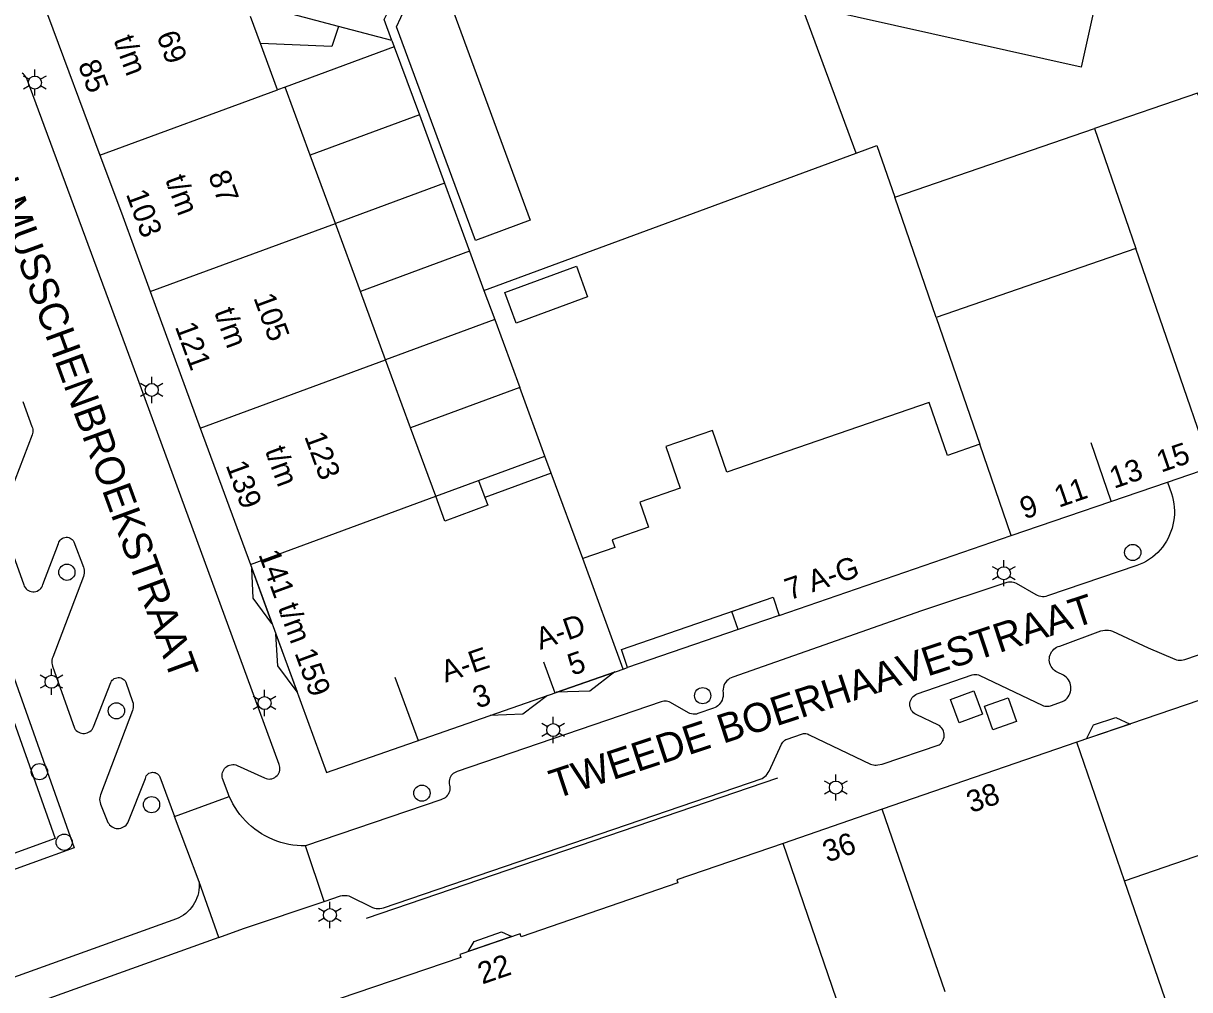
# Model space of a CAD drawing. Extents: x 122462 to 123306, y 485548 to 486417.
# Drawn here: x 122543.2 to 122623.8, y 485773.2 to 485839.9 of the extents above; entities that cross this region are included whole.
import ezdxf

# ---------------------------------------------------------------- set-up
doc = ezdxf.new("R2010")
doc.units = 0
for name, color, linetype in [('Level 1', 7, 'Continuous'), ('Level 10', 7, 'Continuous'), ('Level 17', 7, 'Continuous'), ('Level 19', 7, 'Continuous'), ('Level 2', 7, 'Continuous'), ('Level 22', 7, 'Continuous'), ('Level 23', 7, 'Continuous'), ('Level 24', 7, 'Continuous'), ('Level 4', 7, 'Continuous'), ('Level 42', 7, 'Continuous'), ('Level 45', 7, 'Continuous'), ('Level 5', 7, 'Continuous'), ('Level 50', 7, 'Continuous'), ('Level 53', 7, 'Continuous'), ('Level 58', 7, 'Continuous'), ('Level 59', 7, 'Continuous')]:
    doc.layers.add(name, color=color, linetype=linetype)

msp = doc.modelspace()

# ---------------------------------------------------------------- linework, layer by layer
at = {"layer": 'Level 1'}
for p, q in [((122559.59, 485838.478), (122558.901, 485840.349)), ((122560.77, 485835.277), (122559.59, 485838.478)), ((122561.299, 485835.472), (122560.77, 485835.277)), ((122563.031, 485830.771), (122561.299, 485835.472)), ((122617.208, 485832.614), (122620.063, 485824.326)), ((122564.766, 485826.061), (122563.031, 485830.771)), ((122566.498, 485821.36), (122564.766, 485826.061)), ((122620.063, 485824.326), (122606.271, 485819.574)), ((122551.983, 485821.351), (122555.439, 485811.934)), ((122568.234, 485816.648), (122566.498, 485821.36)), ((122606.271, 485819.574), (122609.291, 485810.81)), ((122569.966, 485811.947), (122568.234, 485816.648)), ((122555.439, 485811.934), (122558.897, 485802.507)), ((122571.706, 485807.226), (122569.966, 485811.947)), ((122622.246, 485808.207), (122625.259, 485809.239)), ((122579.676, 485808.83), (122575.095, 485807.142)), ((122581.851, 485802.93), (122579.676, 485808.83)), ((122611.459, 485804.509), (122622.246, 485808.207)), ((122584.64, 485795.299), (122584.954, 485795.401)), ((122624.403, 485793.12), (122615.979, 485790.239)), ((122615.979, 485790.239), (122602.549, 485785.62)), ((122602.549, 485785.62), (122595.705, 485783.261)), ((122622.308, 485771.864), (122619.273, 485780.677))]:
    msp.add_line(p, q, dxfattribs=at)
for points in [[(122546.889, 485845.419), (122544.88, 485840.66), (122544.88, 485840.489), (122548.508, 485830.759)], [(122633.776, 485812.174), (122633.562, 485812.799), (122633.411, 485812.748), (122629.727, 485823.472), (122624.31, 485835.061), (122617.208, 485832.614)], [(122548.508, 485830.759), (122549.989, 485826.779), (122551.983, 485821.351)], [(122609.291, 485810.81), (122607.042, 485810.035), (122605.779, 485813.701), (122591.812, 485808.889), (122590.818, 485811.775), (122587.595, 485810.664), (122588.589, 485807.778), (122585.805, 485806.819), (122586.404, 485805.081), (122583.892, 485804.215), (122584.071, 485803.695), (122581.851, 485802.93)], [(122575.095, 485807.142), (122575.295, 485806.599), (122572.338, 485805.51), (122571.706, 485807.226)], [(122584.954, 485795.401), (122584.524, 485796.649), (122595.002, 485800.25), (122595.429, 485798.999), (122611.459, 485804.509)], [(122558.897, 485802.507), (122564.16, 485788.16), (122584.64, 485795.299)], [(122595.705, 485783.261), (122588.35, 485780.749), (122588.42, 485780.539), (122577.601, 485776.821), (122577.531, 485777.031), (122573.371, 485775.601), (122573.443, 485775.393), (122562.65, 485771.719), (122562.57, 485771.939), (122555.33, 485769.42), (122555.347, 485769.372), (122554.835, 485769.176)], [(122619.273, 485780.677), (122624.837, 485782.58), (122625.179, 485781.58), (122628.017, 485782.551)]]:
    msp.add_lwpolyline(points, dxfattribs=at)
at = {"layer": 'Level 10'}
for points in [[(122560.385, 485798.453), (122559.094, 485800.197), (122558.994, 485802.244), (122560.385, 485798.453)], [(122592.594, 485798.026), (122592.166, 485799.275), (122595.002, 485800.25), (122595.429, 485798.999), (122592.594, 485798.026)], [(122562.118, 485793.73), (122560.794, 485795.514), (122560.66, 485797.702), (122562.118, 485793.73)], [(122580.046, 485793.699), (122584.079, 485795.105), (122582.34, 485793.768), (122580.046, 485793.699)], [(122575.454, 485792.098), (122579.425, 485793.482), (122577.708, 485792.175), (122575.454, 485792.098)], [(122616.657, 485790.472), (122617.13, 485791.436), (122618.682, 485791.946), (122619.676, 485791.504), (122616.657, 485790.472)], [(122573.935, 485775.795), (122574.363, 485776.484), (122576.242, 485777.16), (122576.96, 485776.835), (122573.935, 485775.795)]]:
    msp.add_lwpolyline(points, dxfattribs=at)
at = {"layer": 'Level 17'}
for p, q in [((122553.649, 485785.113), (122557.439, 485786.507)), ((122555.35, 485780.611), (122553.649, 485785.113)), ((122563.992, 485779.259), (122562.705, 485783.088)), ((122556.723, 485776.778), (122555.35, 485780.611))]:
    msp.add_line(p, q, dxfattribs=at)
for points in [[(122557.439, 485786.507), (122557.356, 485786.712), (122556.978, 485787.74), (122556.954, 485787.843), (122556.946, 485787.949), (122556.952, 485788.055), (122556.973, 485788.158), (122557.008, 485788.258), (122557.057, 485788.352), (122557.119, 485788.438), (122557.193, 485788.515), (122557.276, 485788.58), (122557.368, 485788.633), (122557.466, 485788.672), (122557.569, 485788.697), (122557.675, 485788.708), (122557.78, 485788.703), (122557.885, 485788.684), (122557.985, 485788.65), (122559.882, 485787.778), (122559.979, 485787.74), (122560.08, 485787.715), (122560.184, 485787.706), (122560.288, 485787.711), (122560.39, 485787.73), (122560.488, 485787.764), (122560.581, 485787.811), (122560.666, 485787.871), (122560.742, 485787.942), (122560.807, 485788.023), (122560.861, 485788.113), (122560.9, 485788.209), (122560.926, 485788.31), (122560.938, 485788.413), (122560.935, 485788.517), (122560.917, 485788.62), (122560.885, 485788.719), (122551.134, 485815.329), (122543.48, 485835.998), (122543.433, 485836.103), (122543.374, 485836.2), (122543.303, 485836.29), (122543.221, 485836.37), (122543.129, 485836.438)], [(122543.169, 485813.762), (122543.806, 485812.041), (122543.84, 485811.948), (122543.862, 485811.851), (122543.872, 485811.752), (122543.868, 485811.652), (122543.852, 485811.554), (122543.823, 485811.459), (122541.734, 485806)], [(122622.246, 485808.207), (122622.516, 485807.422), (122622.588, 485807.188), (122622.646, 485806.951), (122622.688, 485806.71), (122622.716, 485806.467), (122622.729, 485806.222), (122622.726, 485805.978), (122622.708, 485805.734), (122622.675, 485805.491), (122622.627, 485805.252), (122622.565, 485805.015), (122622.488, 485804.783), (122622.396, 485804.556), (122622.291, 485804.336), (122622.172, 485804.122), (122622.04, 485803.916), (122621.896, 485803.718), (122621.739, 485803.53), (122621.571, 485803.352), (122621.393, 485803.185), (122621.204, 485803.029), (122621.007, 485802.885), (122620.8, 485802.754), (122620.586, 485802.636), (122620.365, 485802.531), (122620.138, 485802.44), (122613.966, 485800.341), (122613.853, 485800.309), (122613.737, 485800.292), (122613.62, 485800.289), (122613.504, 485800.301), (122613.39, 485800.328), (122613.28, 485800.368), (122613.176, 485800.422), (122611.817, 485801.199), (122611.713, 485801.246), (122611.603, 485801.279), (122611.49, 485801.298), (122611.376, 485801.302), (122611.262, 485801.291), (122611.15, 485801.266), (122605.264, 485799.309), (122592.215, 485794.747), (122592.099, 485794.699), (122591.991, 485794.637), (122591.891, 485794.562), (122591.801, 485794.474), (122591.723, 485794.377), (122591.657, 485794.27), (122591.606, 485794.156), (122591.569, 485794.036), (122591.547, 485793.913), (122591.541, 485793.788), (122591.559, 485793.658), (122591.561, 485793.526), (122591.548, 485793.395), (122591.52, 485793.267), (122591.478, 485793.142), (122591.425, 485793.035), (122591.359, 485792.935), (122591.282, 485792.844), (122591.195, 485792.763), (122591.099, 485792.693), (122590.994, 485792.634), (122590.884, 485792.589), (122589.817, 485792.222), (122589.708, 485792.193), (122589.596, 485792.179), (122589.483, 485792.182), (122589.371, 485792.199), (122589.263, 485792.233), (122589.161, 485792.281), (122587.921, 485792.982), (122587.834, 485793.025), (122587.743, 485793.057), (122587.649, 485793.077), (122587.552, 485793.086), (122587.456, 485793.083), (122587.36, 485793.068), (122587.267, 485793.042), (122573.18, 485788.218), (122573.083, 485788.187), (122572.992, 485788.144), (122572.908, 485788.087), (122572.832, 485788.02), (122572.767, 485787.943), (122572.713, 485787.857), (122572.672, 485787.765), (122572.644, 485787.667), (122572.63, 485787.567), (122572.63, 485787.376), (122572.662, 485787.273), (122572.68, 485787.167), (122572.684, 485787.059), (122572.674, 485786.951), (122572.65, 485786.846), (122572.613, 485786.745), (122572.563, 485786.649), (122572.501, 485786.561), (122572.427, 485786.482)], [(122541.727, 485805.379), (122543.239, 485801.104), (122543.279, 485801.008), (122543.333, 485800.92), (122543.4, 485800.84), (122543.478, 485800.771), (122543.565, 485800.715), (122543.66, 485800.672), (122543.76, 485800.644), (122543.863, 485800.631), (122543.967, 485800.634), (122544.07, 485800.652), (122544.168, 485800.685), (122544.26, 485800.733), (122544.345, 485800.794), (122544.419, 485800.867), (122544.481, 485800.95), (122544.531, 485801.041), (122544.566, 485801.139), (122545.64, 485803.958), (122545.668, 485804.046), (122545.71, 485804.129), (122545.765, 485804.204), (122545.832, 485804.268), (122545.908, 485804.321), (122545.991, 485804.361), (122546.08, 485804.387), (122546.172, 485804.398), (122546.265, 485804.394), (122546.356, 485804.375), (122546.442, 485804.342), (122546.522, 485804.295), (122546.593, 485804.235), (122546.654, 485804.165), (122546.702, 485804.086), (122547.365, 485802.335), (122547.397, 485802.231), (122547.417, 485802.124), (122547.423, 485802.016), (122547.416, 485801.907), (122547.397, 485801.801), (122547.364, 485801.697), (122545.242, 485796.122), (122545.21, 485796.022), (122545.191, 485795.918), (122545.183, 485795.813), (122545.188, 485795.708)], [(122520.38, 485773.439), (122512.886, 485794.596), (122539.224, 485804.105), (122546.718, 485782.948), (122520.38, 485773.439)], [(122615.57, 485794.082), (122615.551, 485794.204), (122615.517, 485794.323), (122615.469, 485794.437), (122615.409, 485794.544), (122615.336, 485794.644), (122615.253, 485794.735), (122615.159, 485794.815), (122615.057, 485794.884), (122614.639, 485795.073), (122614.535, 485795.13), (122614.439, 485795.199), (122614.352, 485795.28), (122614.276, 485795.37), (122614.211, 485795.469), (122614.159, 485795.576), (122614.12, 485795.688), (122614.096, 485795.803), (122614.085, 485795.921), (122614.089, 485796.04), (122614.108, 485796.157), (122614.141, 485796.27), (122614.187, 485796.379), (122614.246, 485796.482), (122614.318, 485796.576), (122614.4, 485796.661), (122614.492, 485796.736), (122614.593, 485796.798), (122614.7, 485796.848), (122614.813, 485796.884), (122617.641, 485797.928), (122617.773, 485797.965), (122617.909, 485797.986), (122618.046, 485797.991), (122618.182, 485797.98), (122618.317, 485797.953), (122618.447, 485797.911), (122620.917, 485796.772), (122622.749, 485795.975), (122622.863, 485795.937), (122622.981, 485795.914), (122623.101, 485795.904), (122623.221, 485795.909), (122623.34, 485795.928), (122623.456, 485795.961), (122628.489, 485797.693)], [(122545.188, 485795.708), (122545.205, 485795.604), (122545.234, 485795.503), (122546.744, 485791.216), (122546.802, 485791.131), (122546.871, 485791.056), (122546.95, 485790.99), (122547.037, 485790.936), (122547.13, 485790.895), (122547.229, 485790.867), (122547.33, 485790.854), (122547.433, 485790.854), (122547.534, 485790.868), (122547.633, 485790.897), (122547.726, 485790.939), (122547.813, 485790.993), (122547.891, 485791.059), (122547.96, 485791.135), (122548.017, 485791.22), (122548.062, 485791.312), (122549.252, 485794.37), (122549.297, 485794.451), (122549.354, 485794.524), (122549.421, 485794.587), (122549.498, 485794.638), (122549.583, 485794.677), (122549.672, 485794.702), (122549.764, 485794.712), (122549.856, 485794.707), (122549.947, 485794.688), (122550.033, 485794.655), (122550.113, 485794.609), (122550.185, 485794.55), (122550.246, 485794.481), (122550.296, 485794.403), (122550.762, 485793.052), (122550.791, 485792.952), (122550.807, 485792.849), (122550.812, 485792.745), (122550.804, 485792.641), (122550.784, 485792.538), (122550.753, 485792.439), (122548.543, 485786.626), (122548.51, 485786.519), (122548.49, 485786.409), (122548.484, 485786.297), (122548.492, 485786.185), (122548.514, 485786.075), (122548.549, 485785.969), (122549.056, 485784.715), (122549.111, 485784.625), (122549.177, 485784.543), (122549.253, 485784.47), (122549.339, 485784.409), (122549.432, 485784.359), (122549.531, 485784.323), (122549.634, 485784.3), (122549.739, 485784.291), (122549.844, 485784.296), (122549.948, 485784.316), (122550.048, 485784.349), (122550.143, 485784.395), (122550.231, 485784.454), (122550.31, 485784.524), (122550.378, 485784.604), (122550.436, 485784.692), (122551.642, 485787.753), (122551.667, 485787.837), (122551.706, 485787.916), (122551.757, 485787.987), (122551.82, 485788.049), (122551.892, 485788.1), (122551.971, 485788.137), (122552.056, 485788.161), (122552.143, 485788.171), (122552.231, 485788.166), (122552.317, 485788.146), (122552.398, 485788.112), (122552.472, 485788.065), (122552.538, 485788.007), (122552.592, 485787.938), (122552.635, 485787.861), (122553.649, 485785.113)], [(122563.992, 485779.259), (122565.12, 485779.638), (122565.235, 485779.663), (122565.352, 485779.675), (122565.469, 485779.674), (122565.586, 485779.661), (122565.7, 485779.635), (122567.343, 485778.828), (122567.467, 485778.796), (122567.594, 485778.776), (122567.723, 485778.769), (122567.851, 485778.774), (122567.978, 485778.792), (122568.103, 485778.822), (122594.252, 485787.737), (122594.352, 485787.8), (122594.445, 485787.873), (122594.53, 485787.955), (122594.605, 485788.047), (122594.669, 485788.146), (122594.723, 485788.251), (122595.582, 485790.113), (122595.628, 485790.19), (122595.683, 485790.261), (122595.746, 485790.325), (122595.817, 485790.38), (122595.895, 485790.425), (122595.977, 485790.461), (122596.963, 485790.806), (122597.038, 485790.835), (122597.116, 485790.853), (122597.196, 485790.859), (122597.277, 485790.853), (122597.355, 485790.834), (122597.43, 485790.805), (122597.499, 485790.764), (122601.738, 485788.74), (122601.833, 485788.705), (122601.932, 485788.68), (122602.032, 485788.667), (122602.134, 485788.665), (122602.235, 485788.675), (122602.535, 485788.73), (122606.47, 485790.056), (122606.555, 485790.123), (122606.631, 485790.201), (122606.695, 485790.289), (122606.748, 485790.384), (122606.787, 485790.485), (122606.813, 485790.591), (122606.824, 485790.699), (122606.822, 485790.807), (122606.805, 485790.914), (122606.774, 485791.019), (122606.729, 485791.118), (122606.672, 485791.21), (122606.603, 485791.294), (122606.523, 485791.368), (122606.435, 485791.431), (122604.888, 485792.165), (122604.796, 485792.217), (122604.712, 485792.281), (122604.638, 485792.356), (122604.574, 485792.441), (122604.523, 485792.533), (122604.485, 485792.632), (122604.461, 485792.735), (122604.452, 485792.84), (122604.457, 485792.946), (122604.476, 485793.05), (122604.51, 485793.15), (122604.557, 485793.245), (122604.616, 485793.332), (122604.688, 485793.41), (122604.769, 485793.478), (122604.858, 485793.534), (122604.955, 485793.577), (122608.761, 485794.893), (122608.868, 485794.916), (122608.977, 485794.923), (122609.086, 485794.915), (122609.193, 485794.891), (122609.295, 485794.853), (122613.601, 485792.797), (122613.692, 485792.763), (122613.786, 485792.741), (122613.881, 485792.729), (122613.978, 485792.729), (122614.074, 485792.741), (122614.168, 485792.763), (122615.007, 485793.051), (122615.136, 485793.115), (122615.232, 485793.193), (122615.318, 485793.281), (122615.393, 485793.379), (122615.456, 485793.485), (122615.507, 485793.597), (122615.544, 485793.715), (122615.567, 485793.836), (122615.576, 485793.959), (122615.57, 485794.082)], [(122562.705, 485783.088), (122562.416, 485783.092), (122562.127, 485783.11), (122561.839, 485783.143), (122561.554, 485783.191), (122561.271, 485783.253), (122560.992, 485783.33), (122560.718, 485783.421), (122560.448, 485783.526), (122560.184, 485783.645), (122559.926, 485783.777), (122559.676, 485783.922), (122559.433, 485784.079), (122559.199, 485784.249), (122558.974, 485784.431), (122558.758, 485784.623), (122558.552, 485784.827), (122558.357, 485785.041), (122558.174, 485785.265), (122558.002, 485785.498), (122557.842, 485785.739), (122557.695, 485785.988), (122557.56, 485786.244), (122557.439, 485786.507)], [(122572.427, 485786.482), (122572.344, 485786.413), (122572.253, 485786.355), (122572.155, 485786.31), (122572.052, 485786.278), (122562.705, 485783.088)], [(122555.35, 485780.611), (122555.36, 485780.422), (122555.357, 485780.233), (122555.339, 485780.045), (122555.307, 485779.858), (122555.26, 485779.675), (122555.201, 485779.495), (122555.128, 485779.321), (122555.042, 485779.152), (122554.943, 485778.991), (122554.833, 485778.837), (122554.711, 485778.692), (122554.579, 485778.557), (122554.437, 485778.432), (122554.286, 485778.318), (122554.127, 485778.215), (122553.961, 485778.125), (122553.788, 485778.048), (122513.731, 485763.641)], [(122556.723, 485776.778), (122558.424, 485777.388), (122563.992, 485779.259)], [(122556.723, 485776.778), (122517.869, 485762.854)]]:
    msp.add_lwpolyline(points, dxfattribs=at)
at = {"layer": 'Level 19'}
for p, q in [((122564.979, 485839.658), (122559.851, 485841.002)), ((122568.675, 485838.69), (122564.979, 485839.658)), ((122568.838, 485838.249), (122561.299, 485835.472)), ((122568.675, 485838.69), (122568.838, 485838.249)), ((122568.838, 485838.249), (122570.57, 485833.548)), ((122570.57, 485833.548), (122563.031, 485830.771)), ((122570.57, 485833.548), (122572.305, 485828.838)), ((122603.416, 485827.861), (122617.208, 485832.614)), ((122575.031, 485821.439), (122600.735, 485830.91)), ((122572.305, 485828.838), (122564.766, 485826.061)), ((122572.305, 485828.838), (122574.038, 485824.137)), ((122606.271, 485819.574), (122603.416, 485827.861)), ((122574.038, 485824.137), (122566.498, 485821.36)), ((122574.038, 485824.137), (122575.031, 485821.439)), ((122575.031, 485821.439), (122575.773, 485819.426)), ((122575.773, 485819.426), (122568.234, 485816.648)), ((122575.773, 485819.426), (122577.505, 485814.724)), ((122577.505, 485814.724), (122569.966, 485811.947)), ((122579.245, 485810.003), (122577.505, 485814.724)), ((122574.663, 485808.315), (122579.245, 485810.003)), ((122579.676, 485808.83), (122579.245, 485810.003)), ((122571.706, 485807.226), (122574.663, 485808.315)), ((122574.663, 485808.315), (122575.095, 485807.142))]:
    msp.add_line(p, q, dxfattribs=at)
for points in [[(122568.675, 485838.69), (122568.146, 485840.126), (122568.731, 485841.33)], [(122564.979, 485839.658), (122564.522, 485838.267), (122559.59, 485838.478)], [(122600.735, 485830.91), (122602.182, 485831.443), (122603.416, 485827.861)], [(122520.991, 485774.747), (122514.173, 485793.971), (122538.59, 485802.817), (122545.408, 485783.593), (122520.991, 485774.747)]]:
    msp.add_lwpolyline(points, dxfattribs=at)
at = {"layer": 'Level 2'}
for points in [[(122616.29, 485836.845), (122598.241, 485840.86), (122600.637, 485848.095), (122617.676, 485843.074), (122616.29, 485836.845)], [(122574.438, 485824.874), (122569, 485839.633), (122570.199, 485842.231), (122572.797, 485841.032), (122578.235, 485826.273), (122574.438, 485824.874)]]:
    msp.add_lwpolyline(points, dxfattribs=at)
at = {"layer": 'Level 22'}
msp.add_line((122592.594, 485798.026), (122584.954, 485795.401), dxfattribs=at)
at = {"layer": 'Level 23'}
msp.add_lwpolyline([(122600.735, 485830.91), (122597.129, 485840.696), (122600.057, 485849.346)], dxfattribs=at)
at = {"layer": 'Level 24'}
msp.add_line((122566.922, 485778.102), (122595.324, 485787.785), dxfattribs=at)
at = {"layer": 'Level 4'}
for p, q in [((122548.508, 485830.759), (122560.77, 485835.277)), ((122551.983, 485821.351), (122564.766, 485826.061)), ((122625.259, 485809.239), (122620.063, 485824.326)), ((122555.439, 485811.934), (122568.234, 485816.648)), ((122611.459, 485804.509), (122609.291, 485810.81)), ((122558.897, 485802.507), (122571.706, 485807.226)), ((122584.64, 485795.299), (122581.851, 485802.93)), ((122619.273, 485780.677), (122615.979, 485790.239)), ((122606.89, 485773.012), (122602.549, 485785.62)), ((122599.667, 485771.71), (122595.705, 485783.261))]:
    msp.add_line(p, q, dxfattribs=at)
at = {"layer": 'Level 42'}
for points in [[(122607.852, 485791.587), (122607.267, 485793.202), (122608.882, 485793.787), (122609.467, 485792.172), (122607.852, 485791.587)], [(122610.187, 485791.101), (122609.616, 485792.73), (122611.245, 485793.301), (122611.816, 485791.672), (122610.187, 485791.101)]]:
    msp.add_lwpolyline(points, dxfattribs=at)
at = {"layer": 'Level 45'}
msp.add_lwpolyline([(122577.254, 485819.183), (122576.482, 485821.279), (122581.418, 485823.097), (122582.19, 485821.001), (122577.254, 485819.183)], dxfattribs=at)
at = {"layer": 'Level 5'}
for p, q in [((122618.361, 485806.876), (122616.981, 485810.902)), ((122579.149, 485795.799), (122579.937, 485793.661)), ((122568.882, 485794.742), (122570.493, 485790.369))]:
    msp.add_line(p, q, dxfattribs=at)
at = {"layer": 'Level 50'}
for p, q in [((122544.015, 485836.231), (122544.015, 485836.681)), ((122543.625, 485836.006), (122543.235, 485836.231)), ((122544.794, 485836.231), (122544.404, 485836.006)), ((122543.625, 485835.556), (122543.235, 485835.331)), ((122544.015, 485834.881), (122544.015, 485835.331)), ((122544.794, 485835.331), (122544.404, 485835.556)), ((122551.689, 485814.786), (122551.299, 485815.011)), ((122552.079, 485815.011), (122552.079, 485815.461)), ((122552.858, 485815.011), (122552.468, 485814.786)), ((122551.689, 485814.336), (122551.299, 485814.111)), ((122552.079, 485813.661), (122552.079, 485814.111)), ((122552.858, 485814.111), (122552.468, 485814.336)), ((122610.949, 485802.362), (122610.949, 485802.812)), ((122610.559, 485802.137), (122610.169, 485802.362)), ((122611.728, 485802.362), (122611.338, 485802.137)), ((122610.559, 485801.687), (122610.169, 485801.462)), ((122610.949, 485801.012), (122610.949, 485801.462)), ((122611.728, 485801.462), (122611.338, 485801.687)), ((122544.775, 485794.642), (122544.385, 485794.867)), ((122545.165, 485794.867), (122545.165, 485795.317)), ((122545.944, 485794.867), (122545.554, 485794.642)), ((122544.775, 485794.192), (122544.385, 485793.967)), ((122545.165, 485793.517), (122545.165, 485793.967)), ((122545.944, 485793.967), (122545.554, 485794.192)), ((122559.878, 485793.402), (122559.878, 485793.852)), ((122559.488, 485793.177), (122559.098, 485793.402)), ((122560.657, 485793.402), (122560.267, 485793.177)), ((122559.488, 485792.727), (122559.098, 485792.502)), ((122559.878, 485792.052), (122559.878, 485792.502)), ((122560.657, 485792.502), (122560.267, 485792.727)), ((122579.43, 485791.314), (122579.04, 485791.539)), ((122579.82, 485791.539), (122579.82, 485791.989)), ((122580.599, 485791.539), (122580.209, 485791.314)), ((122579.43, 485790.864), (122579.04, 485790.639)), ((122579.82, 485790.189), (122579.82, 485790.639)), ((122580.599, 485790.639), (122580.209, 485790.864)), ((122598.95, 485787.344), (122598.56, 485787.569)), ((122599.34, 485787.569), (122599.34, 485788.019)), ((122600.119, 485787.569), (122599.729, 485787.344)), ((122598.95, 485786.894), (122598.56, 485786.669)), ((122599.34, 485786.219), (122599.34, 485786.669)), ((122600.119, 485786.669), (122599.729, 485786.894)), ((122564.004, 485778.543), (122563.614, 485778.768)), ((122564.394, 485778.768), (122564.394, 485779.218)), ((122565.173, 485778.768), (122564.783, 485778.543)), ((122564.004, 485778.093), (122563.614, 485777.868)), ((122564.394, 485777.418), (122564.394, 485777.868)), ((122565.173, 485777.868), (122564.783, 485778.093))]:
    msp.add_line(p, q, dxfattribs=at)
for centre in [(122544.015, 485835.781), (122552.079, 485814.561), (122610.949, 485801.912), (122545.165, 485794.417), (122559.878, 485792.952), (122579.82, 485791.089), (122599.34, 485787.119), (122564.394, 485778.318)]:
    msp.add_circle(centre, 0.45, dxfattribs=at)
at = {"layer": 'Level 53'}
for centre in [(122619.849, 485803.346), (122546.222, 485801.98), (122590.14, 485793.459), (122549.644, 485792.414), (122544.323, 485788.211), (122552.07, 485785.939), (122570.746, 485786.731), (122546.036, 485783.343)]:
    msp.add_circle(centre, 0.56, dxfattribs=at)

# ---------------------------------------------------------------- texts
at = {"layer": 'Level 58'}
for s, rotation, p in [('t/m', 290.28316, (122549.424, 485838.742)), ('69', 290.28316, (122552.395, 485839.038)), ('85', 290.28316, (122546.973, 485837.035)), ('t/m', 290.28316, (122552.993, 485829.101)), ('87', 290.28316, (122555.964, 485829.398)), ('103', 290.28316, (122550.284, 485828.093)), ('105', 290.14835, (122559.094, 485820.932)), ('t/m', 290.14835, (122556.379, 485819.943)), ('121', 290.14835, (122553.669, 485818.942)), ('123', 290.14835, (122562.603, 485811.366)), ('t/m', 290.14835, (122559.888, 485810.379)), ('15', 18.95385, (122621.805, 485808.849)), ('139', 290.14835, (122557.178, 485809.375)), ('13', 18.95385, (122618.557, 485807.735)), ('11', 18.95385, (122614.739, 485806.427)), ('9', 18.95912, (122612.37, 485805.616)), ('141 t/m 159', 290.14874, (122559.437, 485803.215)), ('7 A-G', 18.96941, (122596.132, 485800.034)), ('A-D', 19.08149, (122578.922, 485796.612)), ('A-E', 19.08149, (122572.375, 485794.346)), ('5', 19.08149, (122581.128, 485794.825)), ('3', 19.08149, (122574.581, 485792.558)), ('38', 18.97486, (122608.678, 485785.35)), ('36', 19.01228, (122598.745, 485781.93)), ('22', 18.93999, (122574.916, 485773.52))]:
    msp.add_text(s, height=1.5, rotation=rotation, dxfattribs=at).set_placement(p)
at = {"layer": 'Level 59'}
for s, rotation, p in [('VAN MUSSCHENBROEKSTRAAT', 290.09669, (122539.233, 485833.343)), ('TWEEDE BOERHAAVESTRAAT', 18.19215, (122579.971, 485786.325))]:
    msp.add_text(s, height=2, rotation=rotation, dxfattribs=at).set_placement(p)

doc.saveas('drawing.dxf')
